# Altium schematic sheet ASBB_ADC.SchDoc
size A4
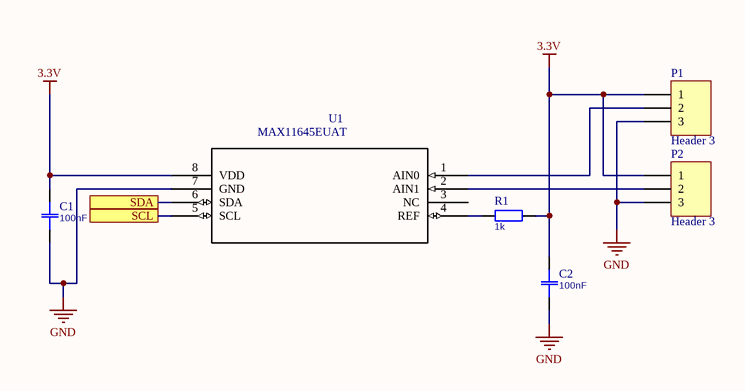
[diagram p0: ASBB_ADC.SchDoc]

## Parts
C1  100nF  [0603]
C2  100nF  [0603]
P1  Header 3  [HDR1X3]
P2  Header 3  [HDR1X3]
R1  1k  [0603]
U1  MAX11645EUAT  [21-0036K]

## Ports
SCL, SDA

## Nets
3.3V: C1.1 C2.1 P1.1 P2.1 R1.1 U1.8(VDD)
GND: C1.2 C2.2 P1.3 P2.3 U1.7(GND)
SCL: U1.5(SCL) ; port SCL
SDA: U1.6(SDA) ; port SDA
NetP1_2: P1.2 U1.1(AIN0)
NetP2_2: P2.2 U1.2(AIN1)
NetR1_2: R1.2 U1.4(REF)

Not connected (* = marked no-connect by the designer): U1 3(NC)

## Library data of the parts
C1 C2 = Capacitor
P1 P2 = Header 3: Header, 3-Pin
R1 = Resistor
U1 = MAX11645EUAT: Data acquisition IC - AD converter _ADC_ Maxim Integrated MAX11645EUA+ External , Internal uMAX 8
